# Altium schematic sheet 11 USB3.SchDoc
size 513 x 386 mm
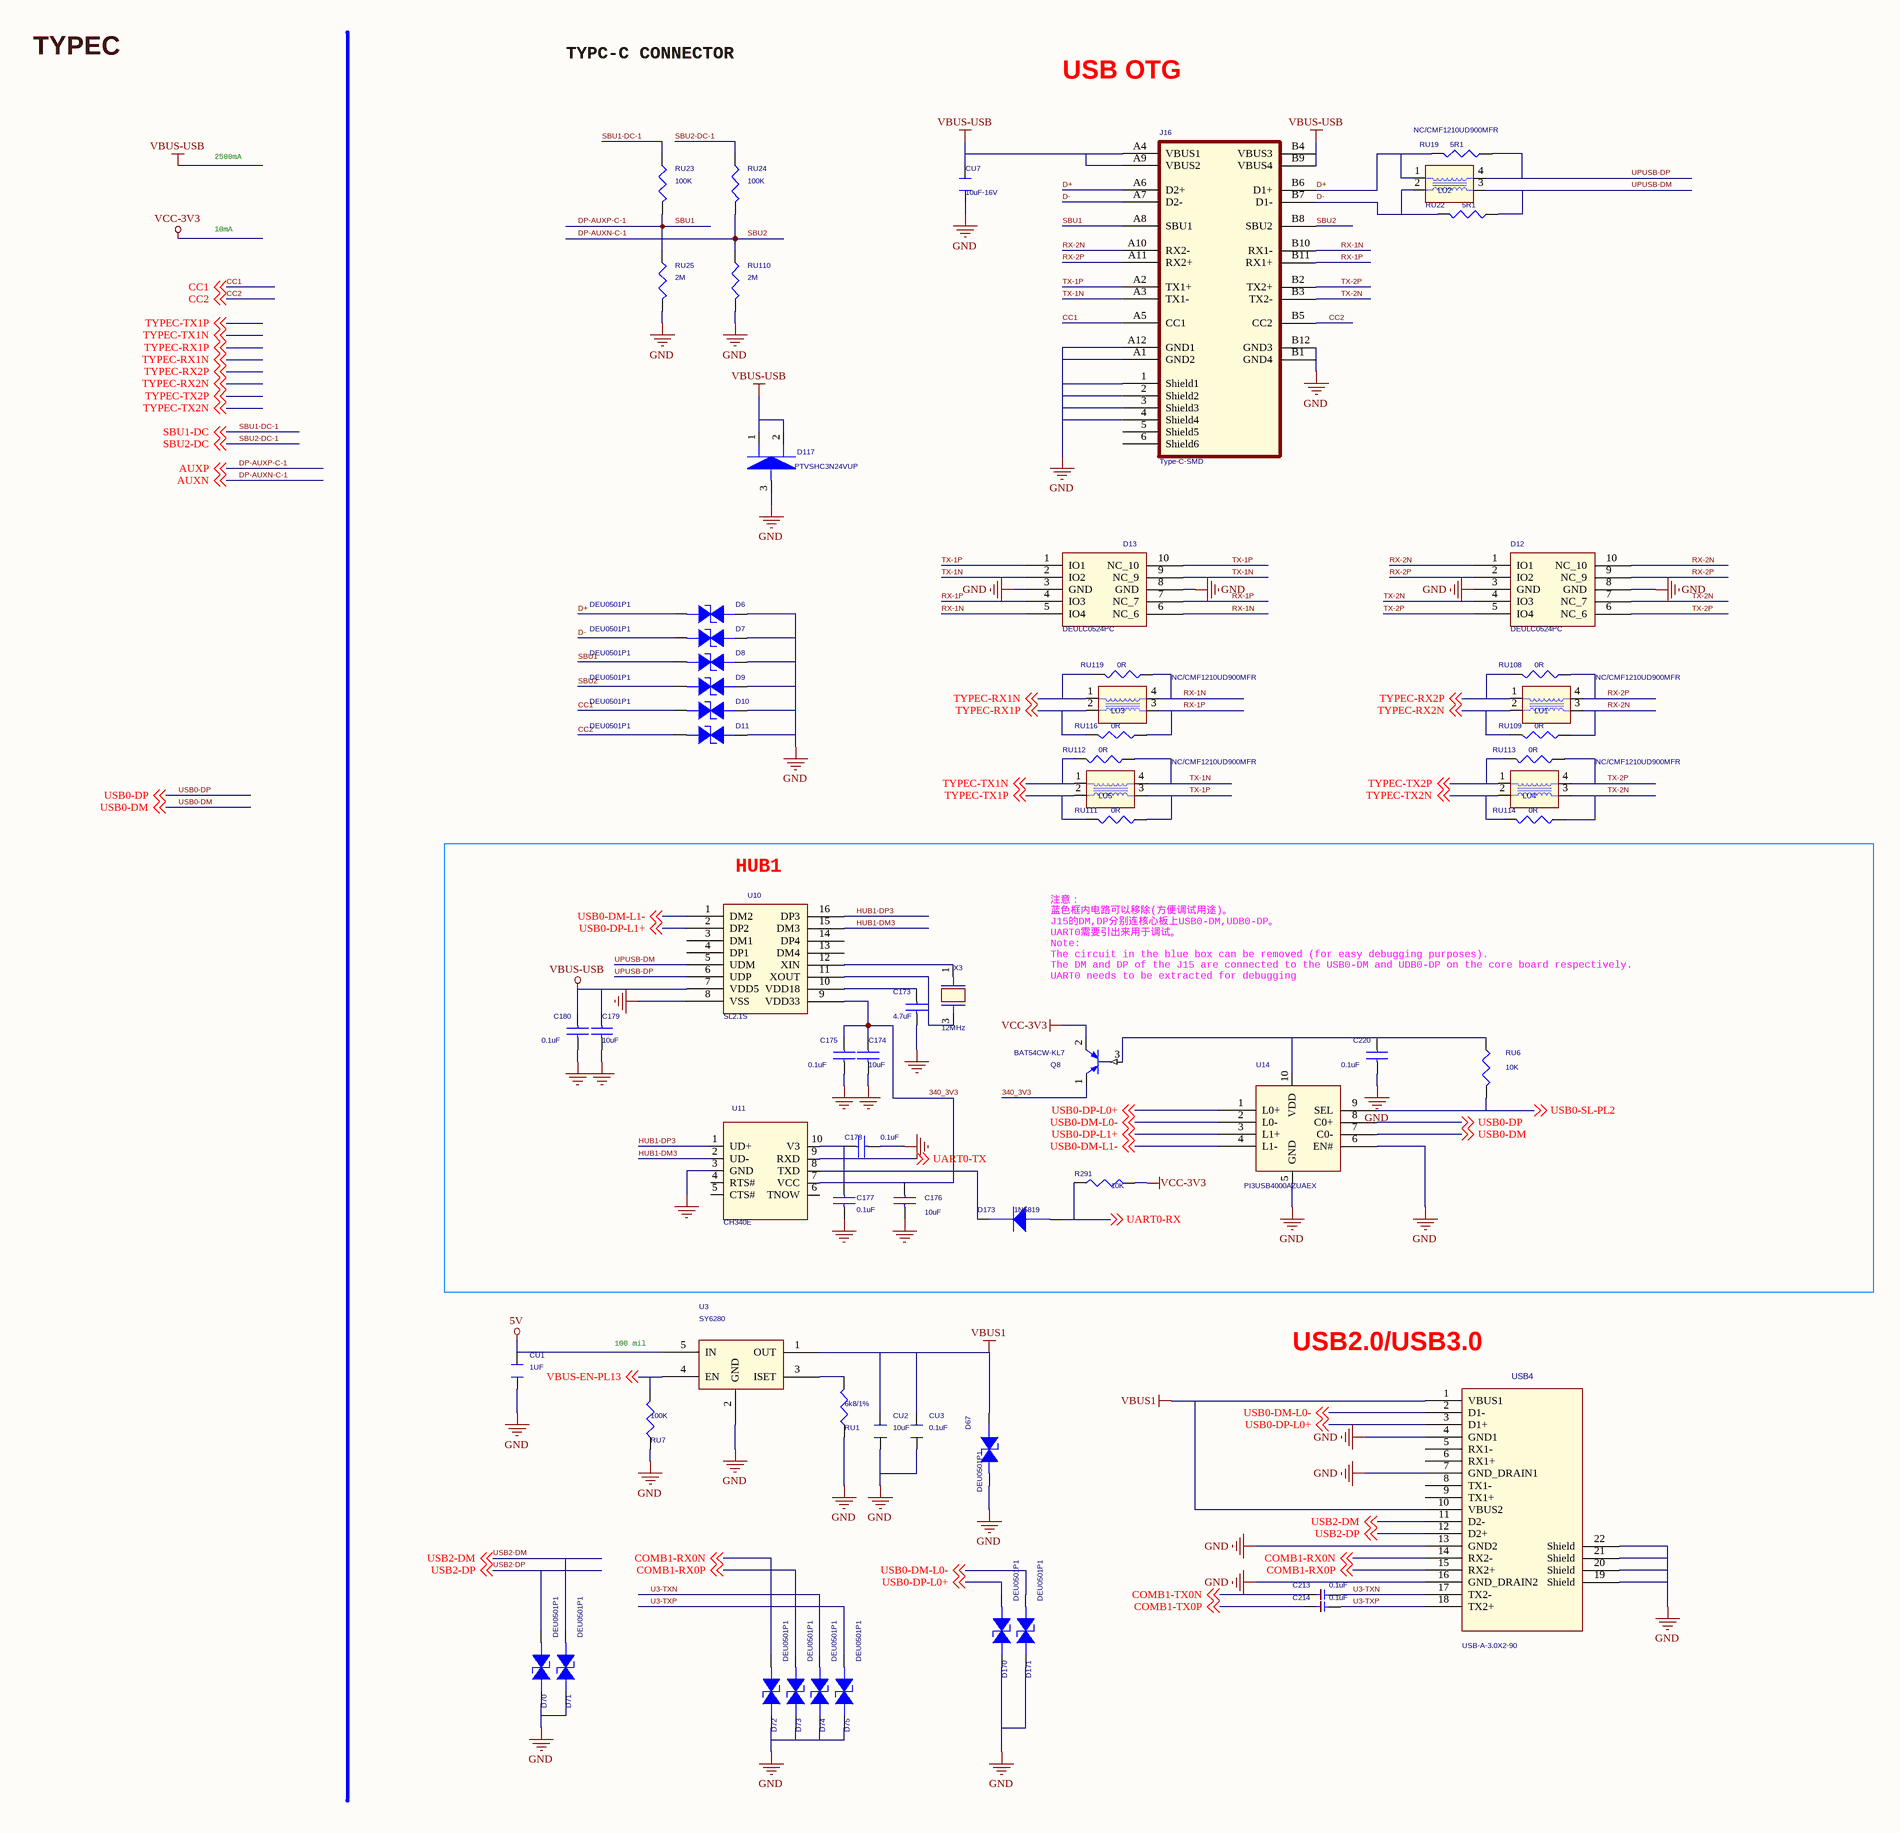
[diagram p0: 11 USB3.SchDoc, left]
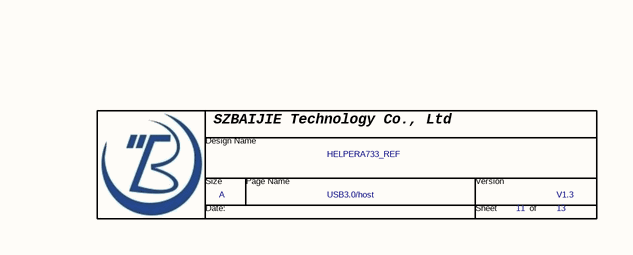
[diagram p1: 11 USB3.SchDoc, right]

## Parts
*  Page Count: 13  Page Number: 11  Page Size: A  Title: HELPERA733_REF  RevCode: V1.3  Doc: USB3.0/host  (hidden comment: TitleBlock0-BJ)  (graphical)
C173  4.7uF  [C0402]
C174  10uF  [C0603]
C175  0.1uF  [C0402]
C176  10uF  [C0603]
C177  0.1uF  [C0402]
C178  0.1uF  [C0402]
C179  10uF  [C0603]
C180  0.1uF  [C0402]
C213  0.1uF  [CCS-0402]
C214  0.1uF  [CCS-0402]
C220  0.1uF  [C0402]
CU1  1UF  [C0402]
CU2  10uF  [C0603]
CU3  0.1uF  [C0402]
CU7  10uF-16V  [C0603]
D6  DEU0501P1  [ESD0402]
D7  DEU0501P1  [ESD0402]
D8  DEU0501P1  [ESD0402]
D9  DEU0501P1  [ESD0402]
D10  DEU0501P1  [ESD0402]
D11  DEU0501P1  [ESD0402]
D12  DEULC0524PC  [DFN2510-10_L2.5-W1.0-P0.50-BL]
D13  DEULC0524PC  [DFN2510-10_L2.5-W1.0-P0.50-BL]
D67  DEU0501P1  [ESD0402]
D70  DEU0501P1  [ESD0402]
D71  DEU0501P1  [ESD0402]
D72  DEU0501P1  [ESD0402]
D73  DEU0501P1  [ESD0402]
D74  DEU0501P1  [ESD0402]
D75  DEU0501P1  [ESD0402]
D117  PTVSHC3N24VUP  [SOD123]
D170  DEU0501P1  [ESD0402]
D171  DEU0501P1  [ESD0402]
D173  1N5819  [SOD323]
J16  Type-C-SMD  [USB28P50B790_894H316]
LU1  NC/CMF1210UD900MFR  Reference: LU1  [ICMS212B900MFR]
LU2  NC/CMF1210UD900MFR  Reference: LU2  [ICMS212B900MFR]
LU3  NC/CMF1210UD900MFR  Reference: LU3  [ICMS212B900MFR]
LU4  NC/CMF1210UD900MFR  Reference: LU4  [ICMS212B900MFR]
LU5  NC/CMF1210UD900MFR  Reference: LU5  [ICMS212B900MFR]
Q8  BAT54CW-KL7  [SOT23]
R291  10K  [R0402]
RU1  6k8/1%  [R0402]
RU6  10K  [R0402]
RU7  100K  [R0402]
RU19  5R1  [R0402]
RU22  5R1  [R0402]
RU23  100K  [R0402]
RU24  100K  [R0402]
RU25  2M  [R0402]
RU108  0R  [R0402]
RU109  0R  [R0402]
RU110  2M  [R0402]
RU111  0R  [R0402]
RU112  0R  [R0402]
RU113  0R  [R0402]
RU114  0R  [R0402]
RU116  0R  [R0402]
RU119  0R  [R0402]
U3  SY6280  [SOP9P1_27B3_90X4_90H1_70]
U10  SL2.1S  [SSOP16_SL2.1S]
U11  CH340E  [SO16]
U14  PI3USB4000AZUAEX  [UQFN-10_L2.0-W1.5-P0.50-BL]
USB4  USB-A-3.0X2-90  [Series B]
X3  12MHz  [XTAL]

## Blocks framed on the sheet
HUB1: C173-C180 C220 D173 Q8 R291 RU6 U10 U11 U14 X3

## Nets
5V: CU1.2 U3.5(IN)
GND: C173.2 C174.2 C175.2 C176.2 C177.2 C178.2 C179.2 C180.2 C220.2 CU1.1 CU2.1 CU3.1 CU7.2 D6.2(CATHODE) D7.2(CATHODE) D8.2(CATHODE) D9.2(CATHODE) D10.2(CATHODE) D11.2(CATHODE) D12.3(GND) D12.8(GND) D13.3(GND) D13.8(GND) D67.1(ANODE) D70.2(CATHODE) D71.2(CATHODE) D72.2(CATHODE) D73.2(CATHODE) D74.2(CATHODE) D75.2(CATHODE) D117.3 D170.2(CATHODE) D171.2(CATHODE) J16.1(Shield1) J16.2(Shield2) J16.3(Shield3) J16.4(Shield4) J16.A1(GND2) J16.A12(GND1) J16.B1(GND4) J16.B12(GND3) RU1.1 RU7.1 RU25.2 RU110.2 U3.2(GND) U10.8(VSS) U11.3(GND) U14.5(GND) U14.6(EN#) USB4.4(GND1) USB4.7(GND_DRAIN1) USB4.13(GND2) USB4.16(GND_DRAIN2) USB4.19(Shield) USB4.20(Shield) USB4.21(Shield) USB4.22(Shield)
VBUS1: CU2.2 CU3.2 D67.2(CATHODE) U3.1(OUT) USB4.1(VBUS1) USB4.10(VBUS2)
VBUS-USB: C179.1 C180.1 CU7.1 D117.1 D117.2 J16.A4(VBUS1) J16.A9(VBUS2) J16.B4(VBUS3) J16.B9(VBUS4) U10.7(VDD5)
VCC-3V3: Q8.2(EMITTER) R291.2
340_3V3: C174.1 C175.1 C176.1 C177.1 C178.1 Q8.1(COLLECTOR) U10.9(VDD33) U11.7(VCC) U11.10(V3)
CC1: D10.1(ANODE) J16.A5(CC1) ; off-sheet CC1
CC2: D11.1(ANODE) J16.B5(CC2) ; off-sheet CC2
COMB1-RX0N: D72.1(ANODE) USB4.14(RX2-) ; off-sheet COMB1-RX0N
COMB1-RX0P: D73.1(ANODE) USB4.15(RX2+) ; off-sheet COMB1-RX0P
COMB1-TX0N: C213.1 ; off-sheet COMB1-TX0N
COMB1-TX0P: C214.1 ; off-sheet COMB1-TX0P
D+: D6.1(ANODE) J16.A6(D2+) J16.B6(D1+) LU2.1 RU19.2
D-: D7.1(ANODE) J16.A7(D2-) J16.B7(D1-) LU2.2 RU22.2
DP-AUXN-C-1: D9.1(ANODE) J16.B8(SBU2) RU24.2 RU110.1 ; off-sheet AUXN  [also labelled AUXN, SBU2]
DP-AUXP-C-1: D8.1(ANODE) J16.A8(SBU1) RU23.2 RU25.1 ; off-sheet AUXP  [also labelled AUXP, SBU1]
HUB1-DM3: U10.15(DM3) U11.2(UD-)
HUB1-DP3: U10.16(DP3) U11.1(UD+)
RX-1N: D13.5(IO4) D13.6(NC_6) J16.B10(RX1-) LU3.4 RU119.1
RX-1P: D13.4(IO3) D13.7(NC_7) J16.B11(RX1+) LU3.3 RU116.1
RX-2N: D12.1(IO1) D12.10(NC_10) J16.A10(RX2-) LU1.3 RU109.1
RX-2P: D12.2(IO2) D12.9(NC_9) J16.A11(RX2+) LU1.4 RU108.1
SBU1-DC-1: RU23.1 ; off-sheet SBU1-DC  [also labelled SBU1-DC]
SBU2-DC-1: RU24.1 ; off-sheet SBU2-DC  [also labelled SBU2-DC]
TX-1N: D13.2(IO2) D13.9(NC_9) J16.A3(TX1-) LU5.4 RU112.1
TX-1P: D13.1(IO1) D13.10(NC_10) J16.A2(TX1+) LU5.3 RU111.1
TX-2N: D12.4(IO3) D12.7(NC_7) J16.B3(TX2-) LU4.3 RU114.1
TX-2P: D12.5(IO4) D12.6(NC_6) J16.B2(TX2+) LU4.4 RU113.1
TYPEC-RX1N: LU3.1 RU119.2 ; off-sheet TYPEC-RX1N
TYPEC-RX1P: LU3.2 RU116.2 ; off-sheet TYPEC-RX1P
TYPEC-RX2N: LU1.2 RU109.2 ; off-sheet TYPEC-RX2N
TYPEC-RX2P: LU1.1 RU108.2 ; off-sheet TYPEC-RX2P
TYPEC-TX1N: LU5.1 RU112.2 ; off-sheet TYPEC-TX1N
TYPEC-TX1P: LU5.2 RU111.2 ; off-sheet TYPEC-TX1P
TYPEC-TX2N: LU4.2 RU114.2 ; off-sheet TYPEC-TX2N
TYPEC-TX2P: LU4.1 RU113.2 ; off-sheet TYPEC-TX2P
U3-TXN: C213.2 D74.1(ANODE) USB4.17(TX2-)
U3-TXP: C214.2 D75.1(ANODE) USB4.18(TX2+)
UART0-RX: D173.1(ANODE) R291.1 ; off-sheet UART0-RX
UART0-TX: U11.9(RXD) ; off-sheet UART0-TX
UPUSB-DM: LU2.3 RU22.1 U10.5(UDM)
UPUSB-DP: LU2.4 RU19.1 U10.6(UDP)
USB0-DM: U14.7(C0-) ; off-sheet USB0-DM
USB0-DM-L0-: D171.1(ANODE) U14.2(L0-) USB4.2(D1-) ; off-sheet USB0-DM-L0-
USB0-DM-L1-: U10.1(DM2) U14.4(L1-) ; off-sheet USB0-DM-L1-
USB0-DP: U14.8(C0+) ; off-sheet USB0-DP
USB0-DP-L0+: D170.1(ANODE) U14.1(L0+) USB4.3(D1+) ; off-sheet USB0-DP-L0+
USB0-DP-L1+: U10.2(DP2) U14.3(L1+) ; off-sheet USB0-DP-L1+
USB0-SL-PL2: RU6.2 U14.9(SEL) ; off-sheet USB0-SL-PL2
USB2-DM: D71.1(ANODE) USB4.11(D2-) ; off-sheet USB2-DM
USB2-DP: D70.1(ANODE) USB4.12(D2+) ; off-sheet USB2-DP
VBUS-EN-PL13: RU7.2 U3.4(EN) ; off-sheet VBUS-EN-PL13
NetC173_1: C173.1 U10.10(VDD18)
NetC220_1: C220.1 Q8.3(BASE) RU6.1 U14.10(VDD)
NetD173_2: D173.2(CATHODE) U11.8(TXD)
NetRU1_2: RU1.2 U3.3(ISET)
NetU10_11: U10.11(XOUT) X3.3
NetU10_12: U10.12(XIN) X3.1

Not connected (* = marked no-connect by the designer): J16 5(Shield5) 6(Shield6); U10 3(DM1) 4(DP1) 13(DM4) 14(DP4); U11 4(RTS#) 5(CTS#) 6(TNOW); USB4 5(RX1-) 6(RX1+) 8(TX1-) 9(TX1+)

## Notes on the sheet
- TYPEC
- TYPC-C CONNECTOR
- USB OTG
- 2500mA
- 10mA
- 注意：
  蓝色框内电路可以移除(方便调试用途)。
  J15的DM,DP分别连核心板上USB0-DM,UDB0-DP。
  UART0需要引出来用于调试。
  Note:
  The circuit in the blue box can be removed (for easy debugging purposes).
  The DM and DP of the J15 are connected to the USB0-DM and UDB0-DP on the core board respectively.
  UART0 needs to be extracted for debugging
- 100 mil
- (near USB4) USB2.0/USB3.0

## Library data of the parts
C173-C175 C179 C180 C220 = CAP NP_Dup1
C176-C178 = CAP NP_Dup2
C213 C214 = C-0402_0
CU1 = C-C0402: ROOM: EMMC; mypage: 08; PAGE: 2
CU2 = C-C0603_Dup1
CU3 = C-C0402: PAGE: 2; mypage: 08; ROOM: EMMC
CU7 = C-C0603
D6-D11 = ESD9B5VL_Dup1: ID: DE-E0001
D12 D13 = ESD_ESD5304D: 4-Lines, Uni-directional, Ultra-low Capacitance Transient Voltage Suppressors; Manufacturer: WillSemi(韦尔半导体); Priority: A
D67 D70-D75 D170 D171 = 1_1.5KE100A_Dup1: 1ST PART DESCRIPTION: WILL ESD9B5V Bidirection ESD Protection
D117 = DIODE SCHOTTKY_6: RoHS 1.0 Ampere Schottky Barrier Rectifiers  SOD-123; OPTIONS: TLL; Material code: 1902-PTVSHC34-0114
D173 = BAS21/SOT_1
J16 = Type-C-CSTU-16022400E_0
LU1-LU5 = ICMS212B900MFR_0
Q8 = PNP DIAC_0
R291 = R_Dup2
RU1 RU6 RU7 = R-R0402-5%_Dup2: mypage: 08; ROOM: EMMC
RU19 RU22-RU25 RU108-RU114 RU116 RU119 = R-R0402-5%_Dup3
U10 = MW7220_QFP64_1
U11 = CH340G_1
U14 = MW7220_QFP64_2
USB4 = USB_1: USB Receptacle; Manufacturer: MPS; Watts: 0.1W; Toler.: 10%; Mfg #1: KEMET; Voltage: 2000V
X3 = XTAL HC49LP 27MHz / MK2743_4: 04 MPN: B18CA1-27.000MHZ; 30 VENDOR: MMD Components; 03 MAN: MMD; 21 FOOTPRINT: HC49 thr. hole d=4.88mm+/-0.2mm; 22 HEIGHT: 3.5mm; 01 IPN: 13-000162-01; 18 SPEED: 27MHz; 20 PACKAGE: HC49; 02 DESC: X-Tal 27.000 MHz 15/30ppm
